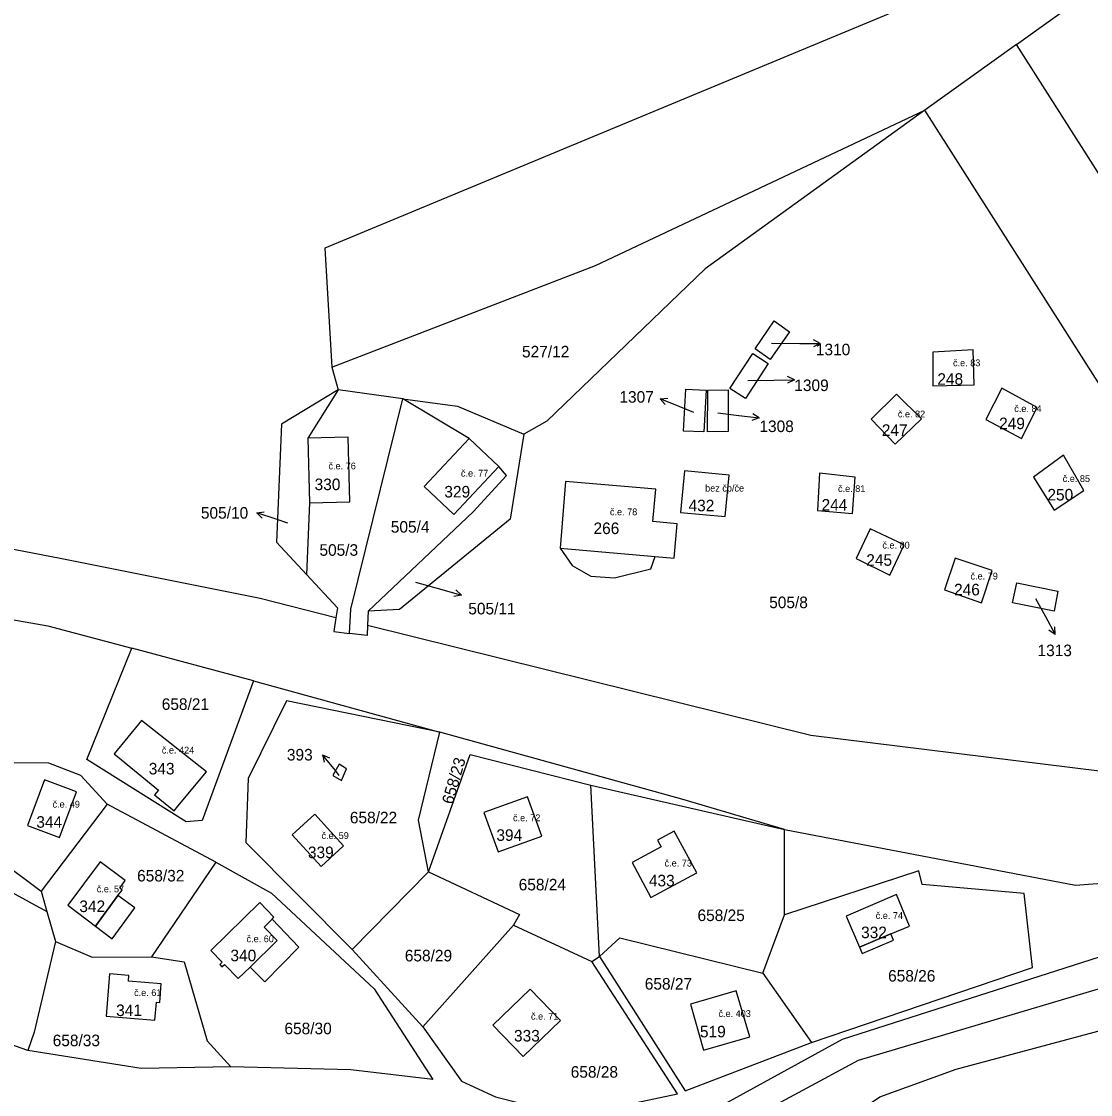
# Model space of a CAD drawing. Extents: x -887272 to -877616, y -1026687 to -1019819.
# Drawn here: x -883802.7 to -883645.6, y -1024093.2 to -1023935.4 of the extents above; entities that cross this region are included whole.
import ezdxf

# ---------------------------------------------------------------- set-up
doc = ezdxf.new("R2010")
doc.units = 0
for name, color, linetype in [('Definiční body', 7, 'Continuous'), ('Hranice parcel', 7, 'Continuous'), ('Parcelní čísla', 7, 'Continuous'), ('Polygon budovy', 7, 'Continuous'), ('Pop  PČ popisy', 7, 'Continuous'), ('Vnitřní kresba', 7, 'Continuous')]:
    doc.layers.add(name, color=color, linetype=linetype)

msp = doc.modelspace()

# ---------------------------------------------------------------- linework, layer by layer
at = {"layer": 'Hranice parcel'}
for p, q in [((-883656.45, -1023938.75), (-883630.8, -1023920.38)), ((-883656.45, -1023938.75), (-883669.93, -1023948.4)), ((-883590.41, -1024042.65), (-883656.45, -1023938.75)), ((-883608.39, -1024045.1), (-883669.93, -1023948.4)), ((-883757.1, -1023986.22), (-883756.18, -1023989.56)), ((-883756.18, -1023989.56), (-883760.62, -1023996.66)), ((-883746.68, -1023990.84), (-883756.18, -1023989.56)), ((-883736.89, -1023996.69), (-883746.68, -1023990.84)), ((-883760.62, -1023996.66), (-883760.36, -1024006.16)), ((-883732.53, -1024000.81), (-883736.89, -1023996.69)), ((-883705.25, -1024001.45), (-883705.83, -1024007.56)), ((-883760.36, -1024006.16), (-883760.82, -1024016.71)), ((-883751.78, -1024022.1), (-883751.85, -1024024.16)), ((-883768.62, -1024032.31), (-883786.49, -1024027.54)), ((-883768.62, -1024032.31), (-883741.24, -1024039.87)), ((-883719.01, -1024047.69), (-883690.56, -1024054.21)), ((-883717.76, -1024072.88), (-883719.01, -1024047.69)), ((-883790.11, -1024050.47), (-883799.82, -1024063.26)), ((-883774.14, -1024058.98), (-883790.11, -1024050.47)), ((-883815.27, -1024051.72), (-883799.82, -1024063.26)), ((-883690.57, -1024066.72), (-883690.56, -1024054.21)), ((-883817.65, -1024056.09), (-883798.98, -1024066.23)), ((-883732.64, -1024057.49), (-883726.22, -1024055.15)), ((-883758.68, -1024059.61), (-883755.37, -1024056.59)), ((-883774.14, -1024058.98), (-883783.59, -1024072.91)), ((-883754.09, -1024071.82), (-883742.91, -1024060.4)), ((-883799.82, -1024063.26), (-883798.98, -1024066.23)), ((-883798.98, -1024066.23), (-883797.72, -1024070.66)), ((-883693.72, -1024075.31), (-883690.57, -1024066.72)), ((-883730.38, -1024068.23), (-883743.71, -1024083.19)), ((-883730.38, -1024068.23), (-883718.88, -1024073.58)), ((-883797.72, -1024070.66), (-883800.86, -1024084)), ((-883754.09, -1024071.82), (-883743.71, -1024083.19)), ((-883718.88, -1024073.58), (-883717.76, -1024072.88)), ((-883693.72, -1024075.31), (-883686.57, -1024085.51)), ((-883801.81, -1024086.66), (-883821.04, -1024079.95)), ((-883800.86, -1024084), (-883801.81, -1024086.66)), ((-883785.14, -1024089.32), (-883801.81, -1024086.66)), ((-883771.96, -1024089.06), (-883785.14, -1024089.32))]:
    msp.add_line(p, q, dxfattribs=at)
for points in [[(-883756.5, -1024023.04), (-883767.66, -1024020.24), (-883797.06, -1024014.34), (-883842.62, -1024005.56), (-883874.8, -1024002.84), (-883906.02, -1023994.68), (-883929.04, -1023982.78), (-884005.12, -1023932.5), (-884033.98, -1023912.56), (-884080.28, -1023877.34), (-884136.58, -1023830.48), (-884162.3, -1023804.42), (-884180.14, -1023781.6), (-884204.86, -1023736.02), (-884224.62, -1023704.92), (-884247.24, -1023674.52), (-884253.66, -1023666.34), (-884254.22, -1023665.64)], [(-883653, -1023925), (-883758.14, -1023968.71), (-883757.1, -1023986.22)], [(-883757.1, -1023986.22), (-883718.33, -1023971.26), (-883669.93, -1023948.4)], [(-883669.93, -1023948.4), (-883702.2, -1023971.74), (-883725.5, -1023994.16), (-883728.86, -1023996.08)], [(-883692.06, -1023979.41), (-883689.83, -1023980.99), (-883692.66, -1023985.08), (-883694.85, -1023983.5), (-883692.06, -1023979.41)], [(-883696.29, -1023990.83), (-883698.57, -1023989.35), (-883695.21, -1023984.2), (-883692.94, -1023985.66), (-883696.29, -1023990.83)], [(-883668.72, -1023988.96), (-883662.66, -1023988.8), (-883662.82, -1023983.66), (-883668.76, -1023983.98), (-883668.72, -1023988.96)], [(-883756.18, -1023989.56), (-883764.52, -1023994.6), (-883765.26, -1024011.96), (-883760.82, -1024016.71)], [(-883705.41, -1023995.64), (-883705.06, -1023989.43), (-883702.05, -1023989.57), (-883702.41, -1023995.71), (-883705.41, -1023995.64)], [(-883698.81, -1023995.68), (-883701.86, -1023995.72), (-883701.8, -1023989.58), (-883698.81, -1023989.56), (-883698.81, -1023995.68)], [(-883660.94, -1023993.92), (-883655.72, -1023996.7), (-883653.38, -1023992.12), (-883658.58, -1023989.3), (-883660.94, -1023993.92)], [(-883754.5, -1024025.36), (-883754.29, -1024021.81), (-883746.68, -1023990.84)], [(-883746.68, -1023990.84), (-883738.64, -1023991.96), (-883728.86, -1023996.08)], [(-883674.06, -1023990.16), (-883677.82, -1023993.84), (-883674.3, -1023997.54), (-883670.42, -1023993.82), (-883674.06, -1023990.16)], [(-883728.86, -1023996.08), (-883730.9, -1024008.58), (-883747.14, -1024021.86), (-883751.78, -1024022.1)], [(-883760.36, -1024006.16), (-883754.46, -1024006), (-883754.7, -1023996.5), (-883760.62, -1023996.66)], [(-883736.89, -1023996.69), (-883743.54, -1024003.74), (-883739.18, -1024007.85), (-883732.53, -1024000.81)], [(-883646.54, -1024004.34), (-883649.54, -1023999.13), (-883653.96, -1024002.38), (-883650.88, -1024007.22), (-883646.54, -1024004.34)], [(-883751.78, -1024022.1), (-883736.3, -1024007.5), (-883731.4, -1024002.14), (-883732.53, -1024000.81)], [(-883705.83, -1024007.56), (-883699.25, -1024008.18), (-883698.7, -1024002.1), (-883705.25, -1024001.45)], [(-883680.54, -1024007.74), (-883680.16, -1024002.36), (-883685.4, -1024001.8), (-883685.72, -1024007.26), (-883680.54, -1024007.74)], [(-883706.76, -1024014.3), (-883706.31, -1024009.22), (-883709.9, -1024008.9), (-883709.48, -1024004.13), (-883722.73, -1024003.02), (-883723.54, -1024012.82)], [(-883899.62, -1024008.57), (-883860.9, -1024017.44), (-883848.52, -1024018.46), (-883830.95, -1024018.96), (-883822.3, -1024020.14), (-883798.84, -1024024.24), (-883786.49, -1024027.54)], [(-883675.06, -1024016.78), (-883672.96, -1024012.34), (-883677.96, -1024009.96), (-883680, -1024014.34), (-883675.06, -1024016.78)], [(-883723.54, -1024012.82), (-883721.76, -1024015.36), (-883719, -1024016.96), (-883715.56, -1024017.2), (-883710.18, -1024015.86), (-883709.57, -1024014.05), (-883706.76, -1024014.3)], [(-883661.58, -1024020.86), (-883660.02, -1024016.12), (-883665.48, -1024014.3), (-883667.02, -1024018.94), (-883661.58, -1024020.86)], [(-883760.82, -1024016.71), (-883756.28, -1024021.58), (-883756.5, -1024023.04)], [(-883650.34, -1024019.14), (-883650.92, -1024022.08), (-883657.05, -1024020.84), (-883656.37, -1024017.92), (-883650.34, -1024019.14)], [(-883756.5, -1024023.04), (-883756.81, -1024025.08), (-883754.5, -1024025.36)], [(-883751.85, -1024024.16), (-883751.9, -1024025.67), (-883754.5, -1024025.36)], [(-883751.85, -1024024.16), (-883686.7, -1024040.32), (-883639.5, -1024046.16), (-883608.39, -1024045.1)], [(-883768.62, -1024032.31), (-883776.16, -1024052.87), (-883778.5, -1024053.04), (-883793.12, -1024043.9), (-883786.49, -1024027.54)], [(-883741.24, -1024039.87), (-883763.79, -1024035.29), (-883769.42, -1024046.7), (-883769.72, -1024056.1), (-883754.09, -1024071.82)], [(-883785.08, -1024038.15), (-883789.08, -1024043.05), (-883782.58, -1024048.4), (-883783.15, -1024049.1), (-883780.27, -1024051.42), (-883779.72, -1024050.76), (-883775.54, -1024045.69), (-883785.08, -1024038.15)], [(-883742.91, -1024060.4), (-883744.38, -1024052.83), (-883741.24, -1024039.87)], [(-883690.56, -1024054.21), (-883705.64, -1024049.74), (-883741.24, -1024039.87)], [(-883742.91, -1024060.4), (-883736.76, -1024043.15), (-883719.01, -1024047.69)], [(-883790.11, -1024050.47), (-883793.99, -1024046.26), (-883798.72, -1024044.43), (-883812.43, -1024044.32), (-883815.27, -1024051.72)], [(-883756.02, -1024044.56), (-883756.96, -1024046.24), (-883755.66, -1024047), (-883754.92, -1024045.28), (-883756.02, -1024044.56)], [(-883794.66, -1024048.64), (-883799.35, -1024046.89), (-883801.84, -1024053.6), (-883797.16, -1024055.35), (-883794.66, -1024048.64)], [(-883726.22, -1024055.15), (-883728.32, -1024049.39), (-883734.77, -1024051.7), (-883732.64, -1024057.49)], [(-883755.37, -1024056.59), (-883759.61, -1024051.94), (-883762.92, -1024054.96), (-883758.68, -1024059.61)], [(-883708.66, -1024056.73), (-883712.97, -1024059.05), (-883710.18, -1024064.2), (-883703.46, -1024060.56), (-883706.77, -1024054.45), (-883709.2, -1024055.74), (-883708.66, -1024056.73)], [(-883690.56, -1024054.21), (-883647.79, -1024062.38), (-883637.46, -1024061.6)], [(-883788.54, -1024063.9), (-883787.94, -1024063.09), (-883788.29, -1024062.81), (-883787.49, -1024061.68), (-883791.17, -1024058.95), (-883795.9, -1024065.32), (-883791.86, -1024068.39), (-883789.42, -1024070.24), (-883786.08, -1024065.72), (-883788.54, -1024063.9)], [(-883774.14, -1024058.98), (-883765.97, -1024063.54), (-883750.88, -1024077.62), (-883742.25, -1024090.97), (-883754.31, -1024089.52), (-883771.96, -1024089.06)], [(-883846.21, -1024144.12), (-883816.92, -1024155.06), (-883797.46, -1024159.1), (-883785.24, -1024159.54), (-883770.02, -1024156.86), (-883754.54, -1024149.76), (-883741.82, -1024138.86), (-883718.28, -1024114.56), (-883704.22, -1024101.36), (-883679.66, -1024088.08), (-883640.76, -1024076.54), (-883629.62, -1024072.06), (-883617.24, -1024060.68)], [(-883742.91, -1024060.4), (-883729.52, -1024066.69), (-883730.38, -1024068.23)], [(-883686.57, -1024085.51), (-883654.07, -1024074.47), (-883655.32, -1024063.62), (-883670.29, -1024062.28), (-883670.78, -1024060.24), (-883690.57, -1024066.72)], [(-883637.46, -1024061.6), (-883637.26, -1024068), (-883643.06, -1024072.58), (-883682.06, -1024085.08), (-883705.66, -1024098.02), (-883721, -1024111.1), (-883722.33, -1024112.53)], [(-883679.54, -1024071.48), (-883679.14, -1024072.43), (-883674.54, -1024070.47), (-883674.93, -1024069.55), (-883672.16, -1024068.39), (-883674.07, -1024063.75), (-883681.48, -1024066.91), (-883679.54, -1024071.48)], [(-883773.25, -1024074.38), (-883772.9, -1024074.05), (-883770.89, -1024076.11), (-883769.13, -1024074.41), (-883766.95, -1024076.58), (-883761.97, -1024071.47), (-883765.87, -1024067.35), (-883765.62, -1024067.08), (-883767.68, -1024064.92), (-883774.9, -1024072), (-883773.24, -1024073.7), (-883773.59, -1024074.02), (-883773.25, -1024074.38)], [(-883717.76, -1024072.88), (-883714.76, -1024070.1), (-883693.72, -1024075.31)], [(-883797.72, -1024070.66), (-883792.36, -1024072.96), (-883783.59, -1024072.91)], [(-883750.88, -1024152.74), (-883746.1, -1024149.26), (-883718.1, -1024121.38), (-883676.52, -1024093.5), (-883665.32, -1024089.44), (-883615.24, -1024076.02), (-883604.08, -1024076.62), (-883602.76, -1024070.42), (-883510.71, -1024093.58), (-883510.26, -1024098.08)], [(-883783.59, -1024072.91), (-883778.79, -1024073.63), (-883775.45, -1024085.25), (-883771.96, -1024089.06)], [(-883717.76, -1024072.88), (-883705.16, -1024092.62), (-883686.57, -1024085.51)], [(-883743.71, -1024083.19), (-883738.02, -1024091.21), (-883733.04, -1024093.47), (-883721.8, -1024096.35), (-883706.27, -1024093.05), (-883718.88, -1024073.58)], [(-883787.01, -1024076.49), (-883786.94, -1024075.65), (-883789.78, -1024075.42), (-883790.28, -1024081.65), (-883783.12, -1024082.22), (-883782.9, -1024079.58), (-883782.39, -1024079.62), (-883782.18, -1024076.88), (-883787.01, -1024076.49)], [(-883727.93, -1024077.64), (-883733.43, -1024082.94), (-883728.96, -1024087.58), (-883723.46, -1024082.28), (-883727.93, -1024077.64)], [(-883704.35, -1024079.85), (-883702.47, -1024086.61), (-883695.65, -1024084.69), (-883697.67, -1024077.93), (-883704.35, -1024079.85)]]:
    msp.add_lwpolyline(points, dxfattribs=at)
at = {"layer": 'Polygon budovy'}
for points in [[(-883668.76, -1023983.98), (-883668.72, -1023988.96), (-883662.66, -1023988.8), (-883662.82, -1023983.66)], [(-883658.58, -1023989.3), (-883660.94, -1023993.92), (-883655.72, -1023996.7), (-883653.38, -1023992.12)], [(-883674.06, -1023990.16), (-883677.82, -1023993.84), (-883674.3, -1023997.54), (-883670.42, -1023993.82)], [(-883760.36, -1024006.16), (-883754.46, -1024006), (-883754.7, -1023996.5), (-883760.62, -1023996.66)], [(-883743.54, -1024003.74), (-883739.18, -1024007.85), (-883732.53, -1024000.81), (-883736.89, -1023996.69)], [(-883653.96, -1024002.38), (-883650.88, -1024007.22), (-883646.54, -1024004.34), (-883649.54, -1023999.13)], [(-883705.25, -1024001.45), (-883705.83, -1024007.56), (-883699.25, -1024008.18), (-883698.7, -1024002.1)], [(-883685.4, -1024001.8), (-883685.72, -1024007.26), (-883680.54, -1024007.74), (-883680.16, -1024002.36)], [(-883722.73, -1024003.02), (-883723.54, -1024012.82), (-883709.57, -1024014.05), (-883706.76, -1024014.3), (-883706.31, -1024009.22), (-883709.9, -1024008.9), (-883709.48, -1024004.13)], [(-883672.96, -1024012.34), (-883677.96, -1024009.96), (-883680, -1024014.34), (-883675.06, -1024016.78)], [(-883665.48, -1024014.3), (-883667.02, -1024018.94), (-883661.58, -1024020.86), (-883660.02, -1024016.12)], [(-883775.54, -1024045.69), (-883785.08, -1024038.15), (-883789.08, -1024043.05), (-883782.58, -1024048.4), (-883783.15, -1024049.1), (-883780.27, -1024051.42), (-883779.72, -1024050.76)], [(-883801.84, -1024053.6), (-883797.16, -1024055.35), (-883794.66, -1024048.64), (-883799.35, -1024046.89)], [(-883728.32, -1024049.39), (-883734.77, -1024051.7), (-883732.64, -1024057.49), (-883726.22, -1024055.15)], [(-883762.92, -1024054.96), (-883758.68, -1024059.61), (-883755.37, -1024056.59), (-883759.61, -1024051.94)], [(-883703.46, -1024060.56), (-883706.77, -1024054.45), (-883709.2, -1024055.74), (-883708.66, -1024056.73), (-883712.97, -1024059.05), (-883710.18, -1024064.2)], [(-883788.54, -1024063.9), (-883787.94, -1024063.09), (-883788.29, -1024062.81), (-883787.49, -1024061.68), (-883791.17, -1024058.95), (-883795.9, -1024065.32), (-883791.86, -1024068.39)], [(-883679.54, -1024071.48), (-883674.93, -1024069.55), (-883672.16, -1024068.39), (-883674.07, -1024063.75), (-883681.48, -1024066.91)], [(-883773.59, -1024074.02), (-883773.25, -1024074.38), (-883772.9, -1024074.05), (-883770.89, -1024076.11), (-883769.13, -1024074.41), (-883765.16, -1024070.5), (-883767.03, -1024068.53), (-883765.87, -1024067.35), (-883765.62, -1024067.08), (-883767.68, -1024064.92), (-883774.9, -1024072), (-883773.24, -1024073.7)], [(-883789.78, -1024075.42), (-883790.28, -1024081.65), (-883783.12, -1024082.22), (-883782.9, -1024079.58), (-883782.39, -1024079.62), (-883782.18, -1024076.88), (-883787.01, -1024076.49), (-883786.94, -1024075.65)], [(-883723.46, -1024082.28), (-883727.93, -1024077.64), (-883733.43, -1024082.94), (-883728.96, -1024087.58)], [(-883702.47, -1024086.61), (-883695.65, -1024084.69), (-883697.67, -1024077.93), (-883704.35, -1024079.85)]]:
    msp.add_lwpolyline(points, close=True, dxfattribs=at)
at = {"layer": 'Pop  PČ popisy'}
for p, q in [((-883692.48, -1023982.69), (-883688.29, -1023982.71)), ((-883688.29, -1023982.71), (-883685.29, -1023982.71)), ((-883685.29, -1023982.71), (-883686.29, -1023982.21)), ((-883685.29, -1023982.71), (-883686.29, -1023983.21)), ((-883695.94, -1023988.16), (-883692.1, -1023988.1)), ((-883692.1, -1023988.1), (-883689.1, -1023988.05)), ((-883689.1, -1023988.05), (-883690.11, -1023987.56)), ((-883689.1, -1023988.05), (-883690.09, -1023988.57)), ((-883708.83, -1023990.87), (-883707.72, -1023990.78)), ((-883706.05, -1023991.99), (-883708.83, -1023990.87)), ((-883708.83, -1023990.87), (-883708.09, -1023991.71)), ((-883703.9, -1023992.87), (-883706.05, -1023991.99)), ((-883700.37, -1023992.93), (-883697.25, -1023993.3)), ((-883697.25, -1023993.3), (-883694.27, -1023993.67)), ((-883694.27, -1023993.67), (-883695.33, -1023994.04)), ((-883694.27, -1023993.67), (-883695.2, -1023993.05)), ((-883768.15, -1024007.63), (-883767.05, -1024007.47)), ((-883765.3, -1024008.56), (-883768.15, -1024007.63)), ((-883768.15, -1024007.63), (-883767.36, -1024008.42)), ((-883763.59, -1024009.12), (-883765.3, -1024008.56)), ((-883744.78, -1024017.82), (-883740.93, -1024018.9)), ((-883740.93, -1024018.9), (-883738.05, -1024019.73)), ((-883738.05, -1024019.73), (-883739.15, -1024019.93)), ((-883738.05, -1024019.73), (-883738.87, -1024018.97)), ((-883653.67, -1024020.23), (-883652.2, -1024022.87)), ((-883652.2, -1024022.87), (-883650.74, -1024025.49)), ((-883650.74, -1024025.49), (-883650.79, -1024024.38)), ((-883650.74, -1024025.49), (-883651.67, -1024024.86)), ((-883756.58, -1024045.53), (-883758.47, -1024043.2)), ((-883758.47, -1024043.2), (-883757.45, -1024043.66)), ((-883758.47, -1024043.2), (-883758.23, -1024044.29)), ((-883756, -1024046.26), (-883756.58, -1024045.53))]:
    msp.add_line(p, q, dxfattribs=at)
at = {"layer": 'Vnitřní kresba'}
for p, q in [((-883723.54, -1024012.82), (-883709.57, -1024014.05)), ((-883788.54, -1024063.9), (-883791.86, -1024068.39)), ((-883765.87, -1024067.35), (-883767.03, -1024068.53)), ((-883767.03, -1024068.53), (-883765.16, -1024070.5)), ((-883674.93, -1024069.55), (-883679.54, -1024071.48)), ((-883765.16, -1024070.5), (-883769.13, -1024074.41))]:
    msp.add_line(p, q, dxfattribs=at)

# ---------------------------------------------------------------- texts
at = {"layer": 'Definiční body'}
for s, p in [('č.e. 83', (-883665.77, -1023986.07)), ('č.e. 82', (-883673.88, -1023993.59)), ('č.e. 84', (-883656.77, -1023992.8)), ('č.e. 76', (-883757.59, -1024001.23)), ('č.e. 77', (-883738.12, -1024002.3)), ('č.e. 85', (-883649.65, -1024003.09)), ('bez čp/če', (-883702.22, -1024004.5)), ('č.e. 81', (-883682.68, -1024004.57)), ('č.e. 78', (-883716.21, -1024007.98)), ('č.e. 80', (-883676.16, -1024012.88)), ('č.e. 79', (-883663.2, -1024017.43)), ('č.e. 424', (-883782.09, -1024043.02)), ('č.e. 49', (-883798.16, -1024050.97)), ('č.e. 72', (-883730.46, -1024052.97)), ('č.e. 59', (-883758.62, -1024055.58)), ('č.e. 73', (-883708.18, -1024059.63)), ('č.e. 57', (-883791.66, -1024063.43)), ('č.e. 74', (-883677.14, -1024067.34)), ('č.e. 60', (-883769.64, -1024070.76)), ('č.e. 61', (-883786.17, -1024078.68)), ('č.e. 71', (-883727.82, -1024082.15)), ('č.e. 403', (-883700.26, -1024081.76))]:
    msp.add_text(s, height=1, dxfattribs=at).set_placement(p)
at = {"layer": 'Parcelní čísla'}
for s, p in [('527/12', (-883729.14, -1023984.77)), ('1310', (-883685.94, -1023984.46)), ('1309', (-883689.11, -1023989.72)), ('248', (-883668.08, -1023988.8)), ('1307', (-883714.82, -1023991.43)), ('1308', (-883694.24, -1023995.75)), ('249', (-883659, -1023995.33)), ('247', (-883676.24, -1023996.31)), ('330', (-883759.63, -1024004.29)), ('329', (-883740.56, -1024005.37)), ('244', (-883685.1, -1024007.3)), ('250', (-883651.9, -1024005.81)), ('505/10', (-883776.35, -1024008.48)), ('432', (-883704.66, -1024007.4)), ('505/4', (-883748.43, -1024010.54)), ('266', (-883718.63, -1024010.75)), ('505/3', (-883758.92, -1024013.94)), ('245', (-883678.53, -1024015.41)), ('246', (-883665.62, -1024019.76)), ('505/11', (-883737.04, -1024022.56)), ('505/8', (-883692.8, -1024021.64)), ('1313', (-883653.35, -1024028.7)), ('658/21', (-883782.11, -1024036.6)), ('393', (-883763.71, -1024044.04)), ('343', (-883784.02, -1024046.09)), ('344', (-883800.55, -1024053.93)), ('658/22', (-883754.45, -1024053.28)), ('394', (-883732.91, -1024055.86)), ('339', (-883760.62, -1024058.4)), ('658/32', (-883785.73, -1024061.83)), ('433', (-883710.49, -1024062.55)), ('658/24', (-883729.63, -1024063.14)), ('342', (-883794.22, -1024066.33)), ('658/25', (-883703.34, -1024067.65)), ('332', (-883679.29, -1024070.17)), ('340', (-883772.01, -1024073.56)), ('658/29', (-883746.37, -1024073.58)), ('658/26', (-883675.32, -1024076.55)), ('658/27', (-883711.09, -1024077.73)), ('341', (-883788.81, -1024081.62)), ('658/30', (-883764.07, -1024084.29)), ('658/33', (-883798.14, -1024086.05)), ('333', (-883730.32, -1024085.36)), ('519', (-883702.98, -1024084.75)), ('658/28', (-883721.98, -1024090.68))]:
    msp.add_text(s, height=1.7, dxfattribs=at).set_placement(p)
msp.add_text('658/23', height=1.7, rotation=74, dxfattribs=at).set_placement((-883739.33, -1024050.58))

doc.saveas('drawing.dxf')
